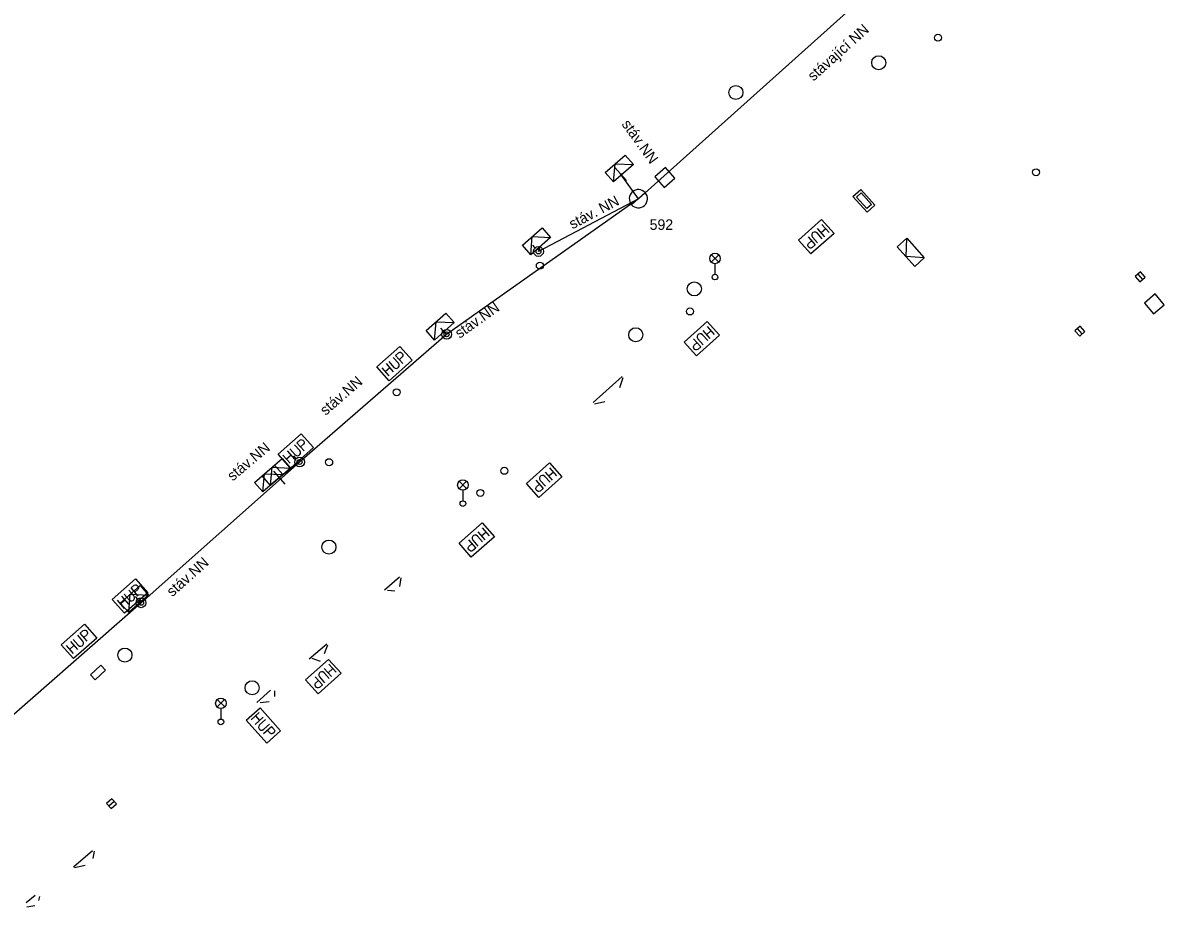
# Model space of a CAD drawing. Extents: x -584388 to -581645, y -1210859 to -1208922.
# Drawn here: x -582354.4 to -582273.1, y -1209663 to -1209600.1 of the extents above; entities that cross this region are included whole.
import ezdxf

# ---------------------------------------------------------------- set-up
doc = ezdxf.new("R2010")
doc.units = 0
for name, color, linetype in [('CIZÍ_NADZEM', 7, 'Continuous'), ('ELE_EON', 7, 'Continuous'), ('ELE_EON_POPIS', 7, 'Continuous')]:
    doc.layers.add(name, color=color, linetype=linetype)

msp = doc.modelspace()

# ---------------------------------------------------------------- linework, layer by layer
at = {"layer": 'CIZÍ_NADZEM'}
for p, q in [((-582308.638, -1209610.384), (-582309.386, -1209611.048)), ((-582309.386, -1209611.048), (-582308.722, -1209611.796)), ((-582308.722, -1209611.796), (-582307.974, -1209611.132)), ((-582307.974, -1209611.132), (-582308.638, -1209610.384)), ((-582305.374, -1209617.118), (-582304.846, -1209616.59)), ((-582304.838, -1209617.115), (-582305.366, -1209616.586)), ((-582305.11, -1209617.23), (-582305.11, -1209617.98)), ((-582275.022, -1209617.98), (-582274.698, -1209618.36)), ((-582273.793, -1209619.385), (-582274.555, -1209620.033)), ((-582274.555, -1209620.033), (-582273.907, -1209620.795)), ((-582273.145, -1209620.147), (-582273.793, -1209619.385)), ((-582273.907, -1209620.795), (-582273.145, -1209620.147)), ((-582278.972, -1209622.215), (-582279.308, -1209621.845)), ((-582323.314, -1209633.248), (-582322.786, -1209632.72)), ((-582322.778, -1209633.245), (-582323.306, -1209632.716)), ((-582323.05, -1209633.36), (-582323.05, -1209634.11)), ((-582340.534, -1209648.788), (-582340.006, -1209648.26)), ((-582339.998, -1209648.785), (-582340.526, -1209648.256)), ((-582340.27, -1209648.9), (-582340.27, -1209649.65)), ((-582348.247, -1209655.836), (-582347.873, -1209655.504))]:
    msp.add_line(p, q, dxfattribs=at)
for points in [[(-582296.64, -1209615.071), (-582298.281, -1209616.537), (-582299.16, -1209615.553), (-582297.52, -1209614.087), (-582296.64, -1209615.071)], [(-582296.988, -1209615.013), (-582297.501, -1209614.439)], [(-582297.48, -1209615.453), (-582297.847, -1209615.041), (-582297.943, -1209614.981), (-582298.042, -1209614.972), (-582298.136, -1209615.006), (-582298.183, -1209615.048), (-582298.228, -1209615.138), (-582298.226, -1209615.234), (-582298.177, -1209615.336), (-582297.809, -1209615.747)], [(-582297.83, -1209614.733), (-582297.317, -1209615.307)], [(-582297.229, -1209614.742), (-582297.559, -1209615.037)], [(-582297.972, -1209615.892), (-582298.185, -1209616.083), (-582298.278, -1209616.117), (-582298.327, -1209616.112), (-582298.398, -1209616.079), (-582298.471, -1209615.997), (-582298.497, -1209615.922), (-582298.496, -1209615.874), (-582298.452, -1209615.785), (-582298.238, -1209615.594)], [(-582298.485, -1209615.318), (-582297.972, -1209615.892)], [(-582304.79, -1209622.321), (-582306.431, -1209623.787), (-582307.31, -1209622.803), (-582305.67, -1209621.337), (-582304.79, -1209622.321)], [(-582305.138, -1209622.263), (-582305.651, -1209621.689)], [(-582305.63, -1209622.703), (-582305.997, -1209622.291), (-582306.093, -1209622.231), (-582306.192, -1209622.222), (-582306.286, -1209622.256), (-582306.333, -1209622.298), (-582306.378, -1209622.388), (-582306.376, -1209622.484), (-582306.327, -1209622.586), (-582305.959, -1209622.997)], [(-582305.98, -1209621.983), (-582305.467, -1209622.557)], [(-582305.379, -1209621.992), (-582305.709, -1209622.287)], [(-582329.17, -1209624.58), (-582327.53, -1209623.113), (-582326.65, -1209624.097), (-582328.29, -1209625.563), (-582329.17, -1209624.58)], [(-582306.122, -1209623.142), (-582306.335, -1209623.333), (-582306.428, -1209623.367), (-582306.477, -1209623.362), (-582306.548, -1209623.329), (-582306.621, -1209623.247), (-582306.647, -1209623.172), (-582306.645, -1209623.124), (-582306.602, -1209623.035), (-582306.388, -1209622.844)], [(-582306.635, -1209622.568), (-582306.122, -1209623.142)], [(-582328.331, -1209624.198), (-582327.963, -1209624.609), (-582327.868, -1209624.669), (-582327.768, -1209624.678), (-582327.674, -1209624.644), (-582327.627, -1209624.602), (-582327.583, -1209624.512), (-582327.584, -1209624.416), (-582327.633, -1209624.315), (-582328.001, -1209623.903)], [(-582327.839, -1209623.758), (-582327.626, -1209623.567), (-582327.532, -1209623.533), (-582327.484, -1209623.538), (-582327.413, -1209623.571), (-582327.339, -1209623.653), (-582327.314, -1209623.728), (-582327.315, -1209623.776), (-582327.359, -1209623.865), (-582327.572, -1209624.056)], [(-582327.325, -1209624.332), (-582327.839, -1209623.758)], [(-582328.823, -1209624.638), (-582328.309, -1209625.212)], [(-582328.581, -1209624.908), (-582328.251, -1209624.614)], [(-582327.98, -1209624.917), (-582328.493, -1209624.343)], [(-582336.199, -1209630.794), (-582334.554, -1209629.333), (-582333.678, -1209630.319), (-582335.322, -1209631.781), (-582336.199, -1209630.794)], [(-582334.865, -1209629.977), (-582334.651, -1209629.787), (-582334.558, -1209629.753), (-582334.509, -1209629.758), (-582334.438, -1209629.791), (-582334.365, -1209629.874), (-582334.34, -1209629.949), (-582334.341, -1209629.997), (-582334.386, -1209630.086), (-582334.599, -1209630.276)], [(-582335.01, -1209631.135), (-582335.522, -1209630.56)], [(-582335.359, -1209630.415), (-582334.992, -1209630.828), (-582334.897, -1209630.888), (-582334.798, -1209630.897), (-582334.704, -1209630.863), (-582334.656, -1209630.821), (-582334.612, -1209630.732), (-582334.613, -1209630.635), (-582334.662, -1209630.534), (-582335.028, -1209630.121)], [(-582334.354, -1209630.552), (-582334.865, -1209629.977)], [(-582335.852, -1209630.853), (-582335.34, -1209631.429)], [(-582335.611, -1209631.125), (-582335.28, -1209630.831)], [(-582316.009, -1209632.394), (-582317.643, -1209633.867), (-582318.527, -1209632.886), (-582316.893, -1209631.414), (-582316.009, -1209632.394)], [(-582316.847, -1209632.779), (-582317.217, -1209632.369), (-582317.312, -1209632.309), (-582317.411, -1209632.301), (-582317.505, -1209632.336), (-582317.552, -1209632.378), (-582317.596, -1209632.467), (-582317.594, -1209632.564), (-582317.545, -1209632.665), (-582317.175, -1209633.075)], [(-582317.201, -1209632.061), (-582316.685, -1209632.633)], [(-582316.6, -1209632.067), (-582316.928, -1209632.363)], [(-582316.357, -1209632.337), (-582316.872, -1209631.765)], [(-582317.337, -1209633.221), (-582317.55, -1209633.412), (-582317.643, -1209633.446), (-582317.691, -1209633.442), (-582317.763, -1209633.409), (-582317.836, -1209633.327), (-582317.862, -1209633.252), (-582317.861, -1209633.204), (-582317.817, -1209633.115), (-582317.605, -1209632.924)], [(-582317.853, -1209632.649), (-582317.337, -1209633.221)], [(-582320.802, -1209636.663), (-582322.453, -1209638.118), (-582323.325, -1209637.127), (-582321.675, -1209635.673), (-582320.802, -1209636.663)], [(-582321.99, -1209636.317), (-582321.481, -1209636.895)], [(-582321.389, -1209636.33), (-582321.721, -1209636.622)], [(-582321.149, -1209636.602), (-582321.658, -1209636.025)], [(-582322.139, -1209637.475), (-582322.354, -1209637.664), (-582322.447, -1209637.697), (-582322.496, -1209637.692), (-582322.567, -1209637.658), (-582322.64, -1209637.576), (-582322.665, -1209637.501), (-582322.663, -1209637.452), (-582322.618, -1209637.364), (-582322.404, -1209637.175)], [(-582322.648, -1209636.897), (-582322.139, -1209637.475)], [(-582321.644, -1209637.039), (-582322.009, -1209636.625), (-582322.104, -1209636.564), (-582322.203, -1209636.554), (-582322.297, -1209636.588), (-582322.344, -1209636.629), (-582322.39, -1209636.719), (-582322.389, -1209636.815), (-582322.341, -1209636.917), (-582321.976, -1209637.331)], [(-582347.998, -1209641.128), (-582346.349, -1209639.672), (-582345.475, -1209640.662), (-582347.125, -1209642.118), (-582347.998, -1209641.128)], [(-582346.662, -1209640.315), (-582346.447, -1209640.126), (-582346.354, -1209640.093), (-582346.305, -1209640.098), (-582346.234, -1209640.132), (-582346.161, -1209640.214), (-582346.136, -1209640.289), (-582346.138, -1209640.337), (-582346.182, -1209640.426), (-582346.397, -1209640.615)], [(-582346.152, -1209640.893), (-582346.662, -1209640.315)], [(-582347.651, -1209641.189), (-582347.142, -1209641.766)], [(-582347.411, -1209641.461), (-582347.08, -1209641.168)], [(-582346.81, -1209641.474), (-582347.32, -1209640.896)], [(-582347.156, -1209640.752), (-582346.791, -1209641.166), (-582346.696, -1209641.226), (-582346.597, -1209641.236), (-582346.503, -1209641.202), (-582346.456, -1209641.161), (-582346.41, -1209641.071), (-582346.412, -1209640.975), (-582346.46, -1209640.873), (-582346.825, -1209640.46)], [(-582351.629, -1209644.351), (-582349.981, -1209642.893), (-582349.106, -1209643.881), (-582350.754, -1209645.339), (-582351.629, -1209644.351)], [(-582350.787, -1209643.973), (-582350.422, -1209644.387), (-582350.327, -1209644.447), (-582350.227, -1209644.457), (-582350.133, -1209644.423), (-582350.086, -1209644.381), (-582350.041, -1209644.292), (-582350.042, -1209644.195), (-582350.091, -1209644.094), (-582350.456, -1209643.68)], [(-582350.293, -1209643.536), (-582350.079, -1209643.346), (-582349.986, -1209643.313), (-582349.937, -1209643.318), (-582349.866, -1209643.351), (-582349.793, -1209643.434), (-582349.768, -1209643.509), (-582349.77, -1209643.557), (-582349.814, -1209643.646), (-582350.028, -1209643.835)], [(-582349.783, -1209644.112), (-582350.293, -1209643.536)], [(-582351.282, -1209644.411), (-582350.771, -1209644.987)], [(-582351.041, -1209644.683), (-582350.71, -1209644.39)], [(-582350.44, -1209644.694), (-582350.951, -1209644.118)], [(-582331.719, -1209646.376), (-582333.355, -1209647.847), (-582334.238, -1209646.865), (-582332.602, -1209645.395), (-582331.719, -1209646.376)], [(-582332.91, -1209646.042), (-582332.396, -1209646.614)], [(-582332.31, -1209646.049), (-582332.638, -1209646.344)], [(-582332.067, -1209646.319), (-582332.582, -1209645.746)], [(-582333.048, -1209647.201), (-582333.261, -1209647.392), (-582333.354, -1209647.426), (-582333.403, -1209647.422), (-582333.474, -1209647.389), (-582333.548, -1209647.307), (-582333.573, -1209647.232), (-582333.572, -1209647.184), (-582333.529, -1209647.095), (-582333.316, -1209646.904)], [(-582333.563, -1209646.629), (-582333.048, -1209647.201)], [(-582332.558, -1209646.76), (-582332.927, -1209646.35), (-582333.022, -1209646.29), (-582333.121, -1209646.281), (-582333.215, -1209646.316), (-582333.262, -1209646.358), (-582333.307, -1209646.448), (-582333.305, -1209646.544), (-582333.255, -1209646.645), (-582332.886, -1209647.056)], [(-582337.487, -1209648.841), (-582336.023, -1209650.483), (-582337.008, -1209651.361), (-582338.472, -1209649.719), (-582337.487, -1209648.841)], [(-582337.546, -1209649.188), (-582338.12, -1209649.7)], [(-582337.826, -1209650.03), (-582337.251, -1209649.518)], [(-582337.817, -1209649.429), (-582337.522, -1209649.759)], [(-582337.106, -1209649.68), (-582337.518, -1209650.048), (-582337.578, -1209650.143), (-582337.588, -1209650.242), (-582337.553, -1209650.336), (-582337.511, -1209650.383), (-582337.422, -1209650.428), (-582337.326, -1209650.426), (-582337.224, -1209650.378), (-582336.812, -1209650.01)], [(-582337.242, -1209650.685), (-582336.667, -1209650.173)], [(-582336.667, -1209650.173), (-582336.477, -1209650.387), (-582336.443, -1209650.48), (-582336.448, -1209650.528), (-582336.481, -1209650.599), (-582336.563, -1209650.673), (-582336.639, -1209650.698), (-582336.687, -1209650.697), (-582336.775, -1209650.653), (-582336.966, -1209650.439)]]:
    msp.add_lwpolyline(points, dxfattribs=at)
for points in [[(-582275.213, -1209618.142), (-582274.889, -1209618.523), (-582274.507, -1209618.198), (-582274.831, -1209617.817)], [(-582278.786, -1209622.046), (-582279.123, -1209621.676), (-582279.494, -1209622.013), (-582279.157, -1209622.383)], [(-582349.215, -1209646.854), (-582348.484, -1209646.172), (-582348.825, -1209645.806), (-582349.556, -1209646.488)], [(-582348.08, -1209656.024), (-582347.706, -1209655.691), (-582348.039, -1209655.316), (-582348.413, -1209655.649)]]:
    msp.add_lwpolyline(points, close=True, dxfattribs=at)
for centre, radius in [((-582289.24, -1209601.14), 0.25), ((-582293.46, -1209602.92), 0.5), ((-582303.62, -1209605.04), 0.5), ((-582282.26, -1209610.72), 0.25), ((-582305.11, -1209616.855), 0.375), ((-582317.57, -1209617.37), 0.25), ((-582305.11, -1209618.18), 0.2), ((-582306.58, -1209619.02), 0.5), ((-582306.89, -1209620.63), 0.25), ((-582310.75, -1209622.29), 0.5), ((-582327.76, -1209626.38), 0.25), ((-582332.57, -1209631.36), 0.25), ((-582320.1, -1209631.97), 0.25), ((-582323.05, -1209632.985), 0.375), ((-582321.81, -1209633.55), 0.25), ((-582323.05, -1209634.31), 0.2), ((-582332.58, -1209637.4), 0.5), ((-582347.1, -1209645.09), 0.5), ((-582338.05, -1209647.42), 0.5), ((-582340.27, -1209648.525), 0.375), ((-582340.27, -1209649.85), 0.2)]:
    msp.add_circle(centre, radius, dxfattribs=at)
at = {"layer": 'ELE_EON'}
for p, q in [((-582312.243, -1209610.371), (-582311.417, -1209611.309)), ((-582310.076, -1209612.166), (-582311.044, -1209613.034)), ((-582317.901, -1209616.097), (-582318.065, -1209615.909)), ((-582324.443, -1209621.999), (-582324.61, -1209621.813)), ((-582334.902, -1209631.088), (-582335.069, -1209630.901)), ((-582335.688, -1209632.93), (-582336.512, -1209631.99)), ((-582346.182, -1209641.108), (-582346.347, -1209640.92))]:
    msp.add_line(p, q, dxfattribs=at)
for points in [[(-582288.01, -1209592.39), (-582310.56, -1209612.6)], [(-582312.324, -1209611.409), (-582312.214, -1209610.114), (-582310.916, -1209610.171)], [(-582310.56, -1209612.6), (-582311.83, -1209610.84), (-582311.62, -1209610.79)], [(-582310.56, -1209612.6), (-582324.21, -1209622.26), (-582324.36, -1209622.04)], [(-582310.56, -1209612.6), (-582317.67, -1209616.36), (-582317.52, -1209615.97)], [(-582318.225, -1209616.588), (-582318.113, -1209615.293), (-582316.815, -1209615.352)], [(-582290.214, -1209616.818), (-582291.51, -1209616.721), (-582291.466, -1209615.422)], [(-582325.059, -1209622.665), (-582324.96, -1209621.369), (-582323.661, -1209621.415)], [(-582324.21, -1209622.26), (-582334.67, -1209631.35)], [(-582313.77, -1209627.1), (-582311.72, -1209625.26)], [(-582311.87, -1209626.05), (-582311.65, -1209625.33)], [(-582312.95, -1209627.06), (-582313.69, -1209627.24)], [(-582334.67, -1209631.35), (-582345.95, -1209641.37), (-582346.13, -1209641.44)], [(-582334.67, -1209631.35), (-582336.1, -1209632.46)], [(-582337.275, -1209633.478), (-582337.163, -1209632.183), (-582335.865, -1209632.242)], [(-582336.735, -1209633.018), (-582336.623, -1209631.723), (-582335.325, -1209631.782)], [(-582328.63, -1209640.45), (-582327.55, -1209639.51)], [(-582327.53, -1209640.2), (-582327.44, -1209639.59)], [(-582346.833, -1209642.06), (-582346.726, -1209640.765), (-582345.427, -1209640.82)], [(-582327.9, -1209640.53), (-582328.41, -1209640.49)], [(-582345.95, -1209641.37), (-582363.49, -1209656.75), (-582363.54, -1209656.65)], [(-582333.99, -1209645.36), (-582332.73, -1209644.28)], [(-582332.9, -1209644.99), (-582332.66, -1209644.36)], [(-582333.19, -1209645.54), (-582333.78, -1209645.33)], [(-582337.72, -1209648.46), (-582336.74, -1209647.58)], [(-582336.44, -1209648.03), (-582336.42, -1209647.64)], [(-582336.83, -1209648.41), (-582337.48, -1209648.49)], [(-582350.77, -1209660.17), (-582349.41, -1209659)], [(-582349.37, -1209659.58), (-582349.26, -1209659.05)], [(-582349.94, -1209660.07), (-582350.69, -1209660.25)], [(-582354.12, -1209662.71), (-582353.48, -1209662.19)], [(-582353.22, -1209662.57), (-582353.15, -1209662.29)], [(-582353.51, -1209662.95), (-582354.07, -1209663.04)]]:
    msp.add_lwpolyline(points, dxfattribs=at)
for points in [[(-582312.918, -1209610.733), (-582311.511, -1209609.495), (-582310.916, -1209610.171), (-582312.324, -1209611.409)], [(-582294.287, -1209613.559), (-582295.289, -1209612.443), (-582294.731, -1209611.942), (-582293.729, -1209613.058)], [(-582294.309, -1209613.31), (-582295.044, -1209612.491), (-582294.709, -1209612.191), (-582293.974, -1209613.01)], [(-582318.818, -1209615.911), (-582317.408, -1209614.675), (-582316.815, -1209615.352), (-582318.225, -1209616.588)], [(-582290.884, -1209617.419), (-582292.136, -1209616.023), (-582291.466, -1209615.422), (-582290.214, -1209616.818)], [(-582325.659, -1209621.994), (-582324.261, -1209620.744), (-582323.661, -1209621.415), (-582325.059, -1209622.665)], [(-582337.328, -1209632.341), (-582335.918, -1209631.105), (-582335.325, -1209631.782), (-582336.735, -1209633.018)], [(-582337.868, -1209632.801), (-582336.458, -1209631.565), (-582335.865, -1209632.242), (-582337.275, -1209633.478)], [(-582347.428, -1209641.386), (-582346.023, -1209640.145), (-582345.427, -1209640.82), (-582346.833, -1209642.06)]]:
    msp.add_lwpolyline(points, close=True, dxfattribs=at)
for centre, radius in [((-582317.67, -1209616.36), 0.35), ((-582317.67, -1209616.36), 0.175), ((-582324.21, -1209622.26), 0.35), ((-582324.21, -1209622.26), 0.175), ((-582334.67, -1209631.35), 0.35), ((-582334.67, -1209631.35), 0.175), ((-582345.95, -1209641.37), 0.35), ((-582345.95, -1209641.37), 0.175)]:
    msp.add_circle(centre, radius, dxfattribs=at)
for start, end in [(41.86769, 221.86769), (221.86769, 41.86769)]:
    msp.add_arc((-582310.56, -1209612.6), 0.65, start, end, dxfattribs=at)

# ---------------------------------------------------------------- texts
at = {"layer": 'ELE_EON_POPIS'}
for s, rotation, p in [('stávající NN', 41.86769, (-582298.11, -1209604.27)), ('stáv.NN', 305.81387, (-582311.79, -1209607.3)), ('stáv. NN', 27.87136, (-582315.25, -1209614.79)), ('stáv.NN', 35.28675, (-582323.28, -1209622.58)), ('stáv.NN', 40.99146, (-582332.82, -1209628.07)), ('stáv.NN', 40.04975, (-582339.43, -1209632.74)), ('stáv.NN', 41.61461, (-582343.73, -1209640.98))]:
    msp.add_text(s, height=0.75, rotation=rotation, dxfattribs=at).set_placement(p)
msp.add_text('592', height=0.75, dxfattribs=at).set_placement((-582309.76, -1209614.82))

doc.saveas('drawing.dxf')
